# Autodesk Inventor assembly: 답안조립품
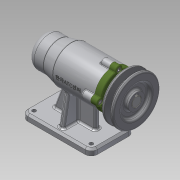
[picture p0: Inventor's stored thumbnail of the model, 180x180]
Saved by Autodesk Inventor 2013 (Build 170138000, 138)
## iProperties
Created: 2019-07
Part Number: 답안조립품
Document SubType Name: Assembly
Designer: Administrator
Author: Administrator
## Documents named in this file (12)
- C:\Users\Administrator\Downloads\490704V1033\답안조립품.iam
- C:\Users\Administrator\Downloads\490704V1033\본체.ipt
- C:\Users\Administrator\Downloads\490704V1033\V벨트풀리.ipt
- C:\Users\Administrator\Downloads\490704V1033\멈춤나사 M3.ipt
- C:\Users\Administrator\Downloads\490704V1033\베어링 6004.ipt
- C:\Users\Administrator\Downloads\490704V1033\베어링 51202.ipt
- C:\Users\Administrator\Downloads\490704V1033\볼트 M4.ipt
- C:\Users\Administrator\Downloads\490704V1033\어댑터슬리브.ipt
- C:\Users\Administrator\Downloads\490704V1033\오일 실.ipt
- C:\Users\Administrator\Downloads\490704V1033\축.ipt
- C:\Users\Administrator\Downloads\490704V1033\커버.ipt
- C:\Users\Administrator\Downloads\490704V1033\키 5 x 5 x 16.ipt
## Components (1 placed, 1 different names)
1. V벨트풀리:1
